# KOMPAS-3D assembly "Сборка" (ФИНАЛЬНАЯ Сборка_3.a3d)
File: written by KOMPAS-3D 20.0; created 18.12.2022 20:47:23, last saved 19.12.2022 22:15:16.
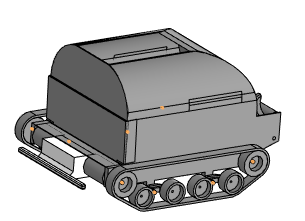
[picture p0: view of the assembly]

Document properties: Полное имя файла: C:\Users\Семья\Desktop\ДЕТАЛИ ДЛЯ СБОРЩИКА БОРЩЕВИКА\ДЕТАЛИ ДЛЯ ФИНАЛА\ФИНАЛЬНАЯ Сборка_3.a3d

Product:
- Part/product: Сборка
    Масса: 1.94625
  - Component [detail]: Деталь  | Масса: 0.238396; source file: Деталь3 БАК С НАСАДКОЙ.m3d
  - Body: Тело 1
      Масса: 1.04943
  - Component [detail]: Деталь  | source file: ..\Деталь.m3d
  - Component [detail]: Деталь  | Масса: 0.563802; source file: Деталь2 БАГАЖНИК_2.m3d
  - Component [detail]: Деталь  | Масса: 0.0587114; source file: ..\Деталь2 ШНЕК_3.m3d
  - Component [detail]: Деталь  | Масса: 0.0612446; source file: ..\Деталь2 ШНЕК_2.m3d
  - Component [detail]: Деталь  | qty 2  | Масса: 0.0558937; source file: Деталь3 ГУСЕНИЦЫ.m3d
  - Component [detail]: Деталь  | qty 8  | Масса: 9.21622e-05; source file: Деталь3 гайка для болта_1.m3d
  - Component [detail]: Деталь  | qty 4  | Масса: 0.000325912; source file: Деталь3 болт для деталь3.1.m3d
  - Component [detail]: Деталь  | qty 2  | Масса: 0.0293022; source file: Деталь2 ОСНОВНОЙ КАТОК_1.m3d
  - Component [detail]: Деталь  | qty 2  | Масса: 0.000750111; source file: Деталь4 БОЛТ.m3d
  - Component [detail]: Деталь  | Масса: 0.421331; source file: ..\Деталь2   КАРКАС_2.m3d
  - Component [detail]: Деталь  | qty 2  | Масса: 0.0746701; source file: ..\МОТОР_1.m3d
  - Component [detail]: Деталь  | Масса: 0.0610303; source file: ..\Деталь2 ДВЕРЦА ДЛЯ БАГАЖНИКА.m3d
  - Component [detail]: Деталь  | qty 2  | Масса: 0.0293022; source file: ..\Деталь2 ОСНОВНОЙ КАТОК_1.m3d
  - Component [detail]: Деталь  | qty 4  | Масса: 0.00248465; source file: ..\Деталь3.2.m3d
  - Component [detail]: Деталь  | qty 4  | Масса: 0.00165643; source file: ..\Деталь3.1.m3d
  - Component [detail]: Деталь  | qty 4  | Масса: 0.0011077; source file: ..\Деталь3 РЕССОРА.m3d
  - Component [detail]: Деталь  | qty 8  | Масса: 0.0166592; source file: ..\Деталь КАТОК.m3d

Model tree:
1. Эскиз:1  (with: Элемент выдавливания:1, Элемент выдавливания:29, Элемент выдавливания:32)
2. Элемент выдавливания:1  (with: Элемент выдавливания:2, Элемент выдавливания:5, Элемент выдавливания:10, Элемент выдавливания:4, Элемент выдавливания:3, Элемент выдавливания:7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)
     Расстояние 1 = 4; Ориентация = 2; Ориентация = 2; Соотношение = 4; Ориентация = 2; Соотношение = 1; Ориентация = 2; Соотношение = 1; Ориентация = 2; Соотношение = 1; Ориентация = 2; Соотношение = 1; Ориентация = 2; Соотношение = 1; Ориентация = 2; Ориентация = 2

Referenced files in C:\Users\Семья\Desktop\ДЕТАЛИ ДЛЯ СБОРЩИКА БОРЩЕВИКА\: Деталь2   КАРКАС_2.m3d, МОТОР_1.m3d, Деталь2 ДВЕРЦА ДЛЯ БАГАЖНИКА.m3d, Деталь2 ОСНОВНОЙ КАТОК_1.m3d, Деталь3.2.m3d, Деталь3.1.m3d, Деталь3 РЕССОРА.m3d, Деталь КАТОК.m3d, Деталь2 ШНЕК_2.m3d, Деталь2 ШНЕК_3.m3d, Деталь.m3d
Referenced files in C:\Users\Семья\Desktop\ДЕТАЛИ ДЛЯ СБОРЩИКА БОРЩЕВИКА\ДЕТАЛИ ДЛЯ ФИНАЛА\: Деталь4 БОЛТ.m3d, Деталь2 ОСНОВНОЙ КАТОК_1.m3d, Деталь3 гайка для болта_1.m3d, Деталь3 болт для деталь3.1.m3d, Деталь3 ГУСЕНИЦЫ.m3d, Деталь2 БАГАЖНИК_2.m3d, Деталь3 БАК С НАСАДКОЙ.m3d
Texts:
  Деталь (1)
  Деталь (2)
  Деталь (3)
  Деталь (4)
  Деталь (5)
  Деталь (6)
  Деталь (7)
  Деталь (8)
